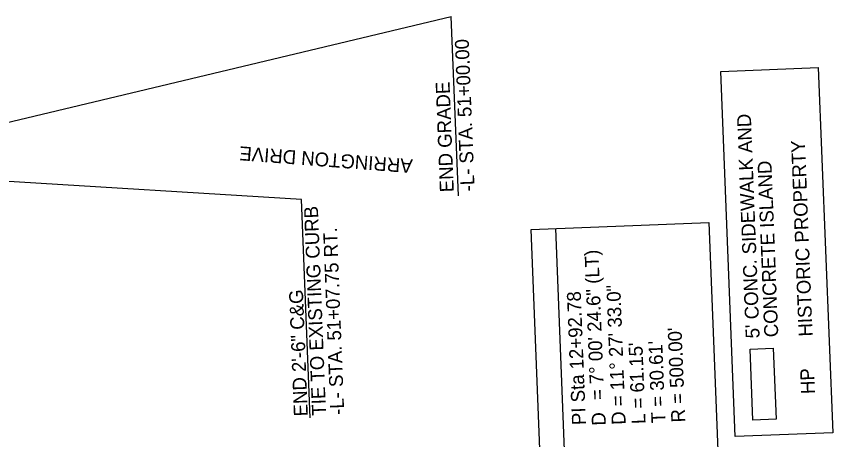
# Model space of a CAD drawing. Extents: x 1627861 to 1629601, y 761281 to 766239.
# Drawn here: x 1628430.8 to 1628841.7, y 765440.1 to 765653.1 of the extents above; entities that cross this region are included whole.
import ezdxf

# ---------------------------------------------------------------- set-up
doc = ezdxf.new("R2010")
doc.units = 0
for name, color, linetype in [('Exist Other Culture Sign Leader', 7, 'Continuous'), ('Exist Utilities Gas UG Line Text', 7, 'Continuous'), ('Exist Utilities Power UG Cable SUE LOS B Cogo Point CELL', 7, 'Continuous'), ('Exist Utilities Water Valve CELL', 7, 'Continuous'), ('Scratch_Level_0', 7, 'Continuous')]:
    doc.layers.add(name, color=color, linetype=linetype)

msp = doc.modelspace()

# ---------------------------------------------------------------- linework, layer by layer
at = {"layer": 'Exist Other Culture Sign Leader'}
msp.add_lwpolyline([(1628792.55, 765441.65), (1628785.31, 765625.35), (1628834.43, 765627.29), (1628841.68, 765443.58)], close=True, dxfattribs=at)
at = {"layer": 'Exist Utilities Gas UG Line Text'}
msp.add_line((1628702.21, 765546.28), (1628710.92, 765325.21), dxfattribs=at)
msp.add_lwpolyline([(1628698.59, 765324.72), (1628689.87, 765545.8), (1628779.41, 765549.33), (1628788.13, 765328.25)], close=True, dxfattribs=at)
at = {"layer": 'Exist Utilities Water Valve CELL'}
msp.add_lwpolyline([(1628801.57, 765449.93), (1628800.16, 765485.67), (1628811.8, 765486.13), (1628813.21, 765450.38)], close=True, dxfattribs=at)
at = {"layer": 'Scratch_Level_0'}
for p, q in [((1628284.31, 765565.93), (1628649.72, 765653.11)), ((1628653.28, 765562.82), (1628649.72, 765653.11)), ((1628574.3, 765561.02), (1628316.13, 765576.73)), ((1628578.64, 765451.01), (1628574.3, 765561.02))]:
    msp.add_line(p, q, dxfattribs=at)

# ---------------------------------------------------------------- texts
at = {"layer": 'Exist Other Culture Sign Leader'}
for s, rotation, p in [('-L- STA. 51+00.00', 92.2582, (1628661.49, 765565.14)), ('END GRADE', 92.2582, (1628651, 765564.73)), ("5' CONC. SIDEWALK AND", 92.2582, (1628804.93, 765491.2)), ('ARRINGTON DRIVE', 175.6964, (1628630.48, 765581.15)), ('HISTORIC PROPERTY', 92.2582, (1628831.59, 765492.1)), ('CONCRETE ISLAND', 92.2582, (1628814.32, 765491.75)), ('HP', 92.2582, (1628832.79, 765463.17))]:
    msp.add_text(s, height=7, rotation=rotation, dxfattribs=at).set_placement(p)
at = {"layer": 'Exist Utilities Gas UG Line Text'}
for s, p in [('= 7%%d 00\' 24.6" (LT)', (1628726.72, 765460.12)), ('D = 11%%d 27\' 33.0"', (1628737.52, 765447.69)), ('PI Sta 12+92.78', (1628717.51, 765447.57)), ("R = 500.00'", (1628767.49, 765448.87)), ("L = 61.15'", (1628747.51, 765448.08)), ("T = 30.61'", (1628757.5, 765448.47)), ('D', (1628727.52, 765447.29))]:
    msp.add_text(s, height=7, rotation=92.2582, dxfattribs=at).set_placement(p)
at = {"layer": 'Exist Utilities Power UG Cable SUE LOS B Cogo Point CELL'}
for s, p in [('TIE TO EXISTING CURB', (1628586.69, 765452.3)), ('-L- STA. 51+07.75 RT.', (1628595.86, 765452.66)), ('END 2\'-6" C&G', (1628577.52, 765451.94))]:
    msp.add_text(s, height=7, rotation=92.2582, dxfattribs=at).set_placement(p)

doc.saveas('drawing.dxf')
